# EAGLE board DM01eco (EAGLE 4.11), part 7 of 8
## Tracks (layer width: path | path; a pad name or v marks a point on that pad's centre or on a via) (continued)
GND  (via drill 0.61) (continued)
  Bottom 0.508: A09.L2 293.37,247.02 293.37,241.94 A09.N2 | v280.04,238.76 280.67,238.12 280.67,235.59 A10.R2 | 267.97,257.81 267.97,254.64 A11.J2 | 267.97,257.81 267.97,259.71 A11.F2 | 267.97,257.81 259.08,266.7 259.08,269.24 A12.C2 | 293.37,257.81 293.37,259.71 A09.F2 | 293.37,257.81 293.37,254.64 A09.J2 | 293.37,257.81 284.48,266.7 284.48,269.24 A10.C2 | v266.7,239.4 267.97,238.12 267.97,235.59 A11.R2 | 280.67,257.81 280.67,254.64 A10.J2 | 280.67,257.81 280.67,259.71 A10.F2 | 280.67,257.81 271.78,266.7 271.78,269.24 A11.C2 | 306.07,257.81 306.07,259.71 A08.F2 | 306.07,257.81 306.07,254.64 A08.J2 306.7,253.37 310.51,253.37 318.77,245.11 | 306.07,257.81 297.18,266.7 297.18,269.24 A09.C2 | 318.77,245.11 318.77,247.02 A07.L2 | 318.77,245.11 318.77,241.94 A07.N2 | 344.17,257.81 344.17,254.64 A05.J2 | 344.17,257.81 344.17,259.71 A05.F2 | 344.17,257.81 335.28,266.7 335.28,269.24 A06.C2 | B16.C2 208.28,199.39 212.09,199.39 213.36,198.12 219.07,198.12 220.34,199.39 B15.C2 220.98,199.39 222.88,199.39 223.52,198.75 225.43,198.75 226.06,198.12 v227.33,198.12 | v243.21,198.75 242.57,198.12 238.76,198.12 237.49,199.39 233.68,199.39 B14.C2 | v290.19,195.58 290.19,196.85 288.29,198.75 285.12,198.75 284.48,199.39 B10.C2 | B13.C2 246.38,199.39 250.19,199.39 251.46,198.12 257.18,198.12 258.44,199.39 B12.C2 259.08,199.39 262.89,199.39 264.16,198.12 269.88,198.12 271.14,199.39 B11.C2 271.14,200.66 271.14,203.2 266.06,208.28 260.99,208.28 248.92,220.34 248.28,220.34 244.47,224.16 244.47,229.24 241.94,231.78 241.94,232.41 237.49,236.86 234.31,236.86 233.68,237.49 A14.P2 | 140.97,236.22 140.97,240.66 A21.N2
  Bottom 0.508: 140.97,236.22 140.97,235.59 A21.R2 141.6,234.31 142.88,233.05 142.88,231.14 144.15,229.87 144.15,226.06 A21.U2 | 153.67,241.94 153.03,242.57 149.86,242.57 145.41,247.02 141.6,247.02 A21.L2 | 153.67,241.94 A20.N2 | A20.N2 153.67,240.66 153.67,235.59 A20.R2 154.31,234.31 155.57,233.05 155.57,231.14 156.84,229.87 156.84,226.06 A20.U2 | 153.67,241.94 153.67,247.02 A20.L2 153.67,248.28 153.67,250.83 151.76,252.73 149.22,252.73 147.32,250.83 140.97,257.18 | 153.67,241.94 A20.N2 | 140.97,257.18 140.97,259.71 A21.F2 140.97,260.99 140.34,261.62 137.16,261.62 132.08,266.7 132.08,269.24 A22.C2 | 140.97,257.18 140.97,254.64 A21.J2 | A21.C2 144.78,269.24 144.78,266.7 149.86,261.62 153.03,261.62 153.67,260.99 A20.F2 | 223.52,231.78 229.24,226.06 229.24,223.52 229.87,222.89 A14.V2 | 223.52,231.78 220.98,234.31 220.98,237.49 A15.P2 | v226.06,234.31 223.52,231.78 | 226.69,254.64 226.06,254.64 v223.52,257.18 214.63,266.06 | 226.69,254.64 229.87,254.64 A14.J2 | 214.63,266.06 212.09,268.6 208.91,268.6 208.28,269.24 A16.C2 207.65,269.24 206.38,267.97 200.66,267.97 199.39,269.24 195.58,269.24 A17.C2 194.94,269.24 193.68,267.97 187.96,267.97 186.69,269.24 182.88,269.24 A18.C2 | 214.63,266.06 217.81,269.24 220.34,269.24 A15.C2 | 226.69,254.64 v236.85,244.47 | 115.57,257.81 115.57,259.71 A23.F2 116.2,260.35 118.11,260.35 121.28,257.18 120.02,255.91 120.02,253.37 137.16,236.22 140.97,236.22 | 115.57,257.81 115.57,254.64 A23.J2 | 115.57,257.81 106.68,266.7 106.68,269.24 A24.C2 | A23.N2 115.57,241.94 115.57,247.02 A23.L2 115.57,248.28 111.76,248.28 102.87,257.18 | 102.87,244.47 102.87,241.94 A24.N2
  Bottom 0.508: 102.87,244.47 102.87,247.02 A24.L2 | 102.87,244.47 111.76,235.59 115.57,235.59 A23.R2 116.2,234.31 117.47,233.05 117.47,226.69 118.11,226.06 118.75,226.06 A23.U2 | 102.87,257.18 102.87,254.64 A24.J2 | 102.87,257.18 102.87,259.71 A24.F2 102.87,260.99 102.23,261.62 99.06,261.62 93.98,266.7 93.98,269.24 A25.C2 | A24.U2 106.05,226.06 102.23,226.06 100.97,227.33 99.06,227.33 97.79,226.06 97.16,226.69 95.89,226.69 92.08,230.5 92.08,233.05 90.81,234.31 A25.R2 90.17,235.59 90.17,240.66 A25.N2 90.17,241.94 89.53,242.57 86.36,242.57 81.92,247.02 78.11,247.02 A26.L2 77.47,248.28 74.3,248.28 66.67,255.91 66.67,258.44 65.41,259.71 A27.F2 65.41,260.99 65.41,263.52 | A26.J2 77.47,254.64 77.47,259.71 A26.F2 77.47,260.99 74.3,260.99 71.75,263.52 | 65.41,263.52 65.41,264.8 67.94,267.33 | 67.94,267.33 69.22,268.6 68.58,269.24 A27.C2 | 65.41,263.52 59.69,269.24 55.88,269.24 A28.C2 | 67.94,267.33 71.75,263.52 | 90.17,257.81 90.17,254.64 A25.J2 | 90.17,257.81 90.17,259.71 A25.F2 | 90.17,257.81 81.28,266.7 81.28,269.24 A26.C2 80.64,269.88 79.38,271.14 71.75,263.52 | B23.C2 119.38,199.39 123.19,199.39 124.46,198.12 130.18,198.12 131.44,199.39 B22.C2 132.08,199.39 135.89,199.39 137.16,198.12 v142.88,198.12 | v100.33,196.22 97.16,199.39 93.98,199.39 B25.C2 | B21.C2 144.78,199.39 148.59,199.39 149.86,198.12 154.94,198.12 156.84,200.03 B20.C2 157.48,199.39 161.29,199.39 168.28,192.41 170.81,192.41 172.72,194.31 170.81,196.22 170.81,198.75 170.18,199.39 B19.C2 | v191.77,198.75 189.23,196.22 186.69,198.75 183.51,198.75 182.88,199.39 B18.C2 | A32.U2 4.45,226.06 4.45,229.87 3.17,231.14 3.17,233.05 1.91,234.31 A32.R2
  Bottom 0.508: A31.U2 17.14,226.06 17.14,229.87 15.88,231.14 15.88,233.05 14.61,234.31 A31.R2 | A31.L2 13.97,247.02 13.97,241.94 A31.N2 | 13.97,257.81 13.97,254.64 A31.J2 | 13.97,257.81 13.97,259.71 A31.F2 | 8.26,263.52 13.97,257.81 | 8.26,263.52 5.08,266.7 5.08,269.24 A32.C2 | 52.07,257.81 52.07,254.64 A28.J2 52.7,253.37 56.52,253.37 64.77,245.11 | 52.07,257.81 52.07,259.71 A28.F2 | 52.07,257.81 43.18,266.7 43.18,269.24 A29.C2 | A30.L2 26.67,247.02 26.67,241.94 A30.N2 | 26.67,257.81 26.67,254.64 A30.J2 | 26.67,257.81 26.67,259.71 A30.F2 | 26.67,257.81 17.78,266.7 17.78,269.24 A31.C2 17.14,269.88 15.88,271.14 8.26,263.52 | v9.53,198.12 8.26,199.39 5.08,199.39 B32.C2 | 35.56,198.12 34.29,199.39 30.48,199.39 B30.C2 | 35.56,198.12 41.27,198.12 42.55,199.39 B29.C2 | 36.83,196.85 35.56,198.12 | 36.83,196.85 v45.72,187.96 48.9,184.78 52.07,184.78 B28.J2 | 36.83,196.85 33.66,193.68 32.38,193.68 27.94,198.12 22.86,198.12 21.59,199.39 17.78,199.39 B31.C2 | 41.27,175.9 41.27,182.25 40.01,183.52 B29.J2 | 41.27,175.9 41.27,173.99 42.55,172.72 42.55,168.91 B29.P2 | A29.U2 42.55,226.06 42.55,227.97 40.01,230.5 40.01,234.31 A29.R2 | A29.L2 39.37,247.02 39.37,241.94 A29.N2 | A26.U2 80.64,226.06 79.38,227.33 79.38,229.24 78.11,230.5 78.11,234.31 A26.R2 77.47,235.59 73.66,235.59 64.77,244.47 | 64.77,244.47 64.77,241.94 A27.N2 | 64.77,244.47 64.77,245.11 | 64.77,245.11 64.77,247.02 A27.L2 | A28.R2 52.07,235.59 52.07,240.66 A28.N2 | v76.2,197.49 73.66,197.49 72.39,198.75 69.22,198.75 68.58,199.39 B27.C2 | v87.63,196.22 85.09,198.75 81.92,198.75 81.28,199.39 B26.C2 | 358.77,198.12 353.06,198.12 351.79,199.39 347.98,199.39 B05.C2 347.35,200.03 345.44,198.12 340.36,198.12 339.09,199.39 335.28,199.39 B06.C2
  Bottom 0.508: 358.77,198.12 360.05,199.39 B04.C2 | v374.65,179.07 374.65,182.88 374.01,183.52 374.01,184.15 | 374.01,184.15 374.01,186.06 373.38,186.69 B03.H2 | v376.56,161.93 371.48,167 371.48,169.55 370.2,170.81 B03.N2 | 367.03,191.14 v368.94,193.04 | 374.01,184.15 367.03,191.14 | 358.77,198.12 359.41,198.12 366.39,191.14 367.03,191.14 | C12.C2 259.08,132.72 260.99,132.72 263.52,135.25 266.06,135.25 267.33,133.98 271.14,133.98 C11.C2 271.78,132.72 275.59,132.72 276.86,131.44 v278.13,131.44 | v379.73,129.54 376.56,132.72 373.38,132.72 C03.C2 | v391.8,128.91 391.16,128.91 389.25,127 386.71,129.54 386.71,132.08 386.08,132.72 C02.C2 | C04.C2 360.05,132.72 356.24,132.72 353.69,130.18 351.79,132.08 348.62,132.08 347.98,132.72 C05.C2 347.35,132.72 346.07,131.44 340.36,131.44 339.09,132.72 335.28,132.72 C06.C2 334.64,132.72 330.83,132.72 329.56,131.44 327.02,131.44 326.39,132.08 323.21,132.08 322.58,132.72 C07.C2 | C10.C2 284.48,132.72 288.29,132.72 289.56,131.44 295.27,131.44 296.55,132.72 C09.C2 | v377.19,140.34 373.38,144.15 373.38,154.94 B03.U2 | C17.C2 195.58,133.98 199.39,133.98 201.93,136.53 203.2,135.25 206.38,135.25 207.65,133.98 C16.C2 208.28,132.72 211.46,132.72 v214.63,129.54 | v227.33,129.54 224.16,132.72 220.98,132.72 C15.C2 | v189.23,129.54 186.69,132.08 183.51,132.08 182.88,132.72 C18.C2 | C24.C2 106.68,133.98 109.86,133.98 113.03,137.16 114.94,135.25 117.47,135.25 118.75,133.98 C23.C2 119.38,132.72 120.02,132.08 123.19,132.08 128.27,127 v130.18,127 | v99.69,131.44 99.06,131.44 97.79,132.72 93.98,132.72 C25.C2 | v11.43,129.54 8.26,132.72 5.08,132.72 C32.C2
  Bottom 0.508: C30.C2 30.48,133.98 33.66,133.98 36.83,137.16 38.73,135.25 40.64,135.25 42.55,133.35 C29.C2 | B29.V2 40.01,151.77 55.24,136.53 55.24,133.98 C28.C2 55.24,132.72 53.98,131.44 48.26,131.44 46.99,132.72 46.35,132.72 | 64.77,156.21 64.77,153.03 B27.V2 | 64.77,156.21 56.52,164.47 56.52,167 55.88,167.64 B28.P2 55.88,168.91 53.98,170.81 53.98,172.09 53.34,172.72 48.26,172.72 45.09,175.9 41.27,175.9 | v68.58,163.83 68.58,167.64 B27.P2 | 64.77,156.21 v65.41,156.84 | 46.35,132.72 43.18,132.72 | 43.18,132.72 C29.C2 | 43.18,132.72 43.81,132.08 40.64,128.91 38.1,128.91 36.83,130.18 34.92,128.27 29.84,128.27 29.21,128.91 25.4,128.91 21.59,132.72 17.78,132.72 C31.C2 | 43.18,132.72 C29.C2 | v74.93,131.44 73.03,131.44 72.39,132.08 69.22,132.08 68.58,132.72 C27.C2 | v239.4,131.44 238.12,131.44 237.49,132.08 234.31,132.08 233.68,132.72 C14.C2 | 112.39,66.67 46.35,132.72
INC_MB  (via drill 0.61)
  Top 0.152: v258.44,34.92 246.38,22.86 243.21,22.86 D13.T2 242.57,21.59 238.76,21.59 v223.52,6.35 | v66.67,12.07 96.52,12.07 101.6,17.14 107.95,17.14 111.76,20.95 114.94,20.95 115.57,21.59 D23.T2 116.2,22.86 117.47,24.13 120.65,24.13 v131.44,34.92 | 179.07,19.05 179.07,21.59 D18.T2 | 179.07,19.05 v163.19,3.18 | v193.04,33.02 179.07,19.05 | v69.85,256.54 66.04,252.73 60.96,252.73 40.01,231.78 40.01,229.24 A29.T2 | v299.72,233.05 295.27,233.05 285.12,222.89 285.12,220.98 v278.13,214 | v241.3,240.66 239.4,240.66 234.95,236.22 234.95,235.59 233.68,234.31 232.41,234.31 224.79,226.69 218.44,226.69 212.09,220.34 209.55,220.34 v207.65,218.44 | v156.84,235.59 156.84,234.95 v128.27,206.38 119.38,197.49 120.65,196.22 120.65,193.04 120.02,192.41 v120.02,191.14 | v76.83,139.06 76.83,141.61 104.78,169.55 110.49,169.55 117.47,176.53 117.47,177.8 119.38,179.71 121.28,179.71 124.46,182.88 125.73,182.88 v127,184.15
  Route2 0.152: v66.67,12.07 66.04,11.43 55.88,21.59 52.7,21.59 D28.T2 | v17.14,77.47 17.14,78.74 38.1,99.7 39.37,99.7 40.64,100.97 40.64,102.87 53.98,116.21 53.98,117.48 55.88,119.38 57.15,119.38 v76.83,139.06
  Route15 0.152: v278.13,214 274.32,214 273.69,213.36 247.01,240.03 241.94,240.03 v241.3,240.66
  Bottom 0.152: v258.44,34.92 276.86,16.51 278.13,16.51 280.04,14.61 285.12,14.61 286.38,13.34 295.91,13.34 296.55,12.7 299.72,12.7 307.34,20.32 306.07,21.59 D08.T2 | v163.19,3.18 v131.44,34.92 | v223.52,6.35 210.19,19.69 209.55,19.69 203.2,26.04 203.2,26.67 196.85,33.02 v193.04,33.02 | v69.85,256.54 72.39,256.54 76.2,252.73 81.92,252.73 102.23,232.41 | 102.23,232.41 102.23,229.87 102.87,229.24 A24.T2 | v299.72,233.05 299.72,232.41 302.89,229.24 306.07,229.24 A08.T2 | v207.65,218.44 202.56,213.36 196.85,219.08 184.78,219.08 180.34,223.52 174.62,223.52 173.99,224.16 168.28,224.16 v156.84,235.59 | v128.27,206.38 102.23,232.41 | v17.14,77.47 15.88,76.2 15.88,68.58 28.57,55.88 28.57,43.18 48.9,22.86 52.07,22.86 D28.T2 | v127,184.15 125.73,184.15 120.02,189.87 v120.02,191.14
IOP1  (via drill 0.61)
  Top 0.152: v403.86,85.09 402.59,83.82 402.59,79.38 403.23,78.74 403.23,73.03 400.69,70.48 400.69,68.58 398.78,66.67 403.86,61.59 403.86,59.69 389.25,45.09 386.08,45.09 D02.K2 | v389.25,169.55 389.89,169.55 400.05,179.71 400.05,183.52 399.42,184.15 400.05,184.78 400.05,185.42 v405.13,190.5 | v368.3,234.95 368.3,236.22 381,248.92 384.18,248.92 385.44,250.19 A02.K2
  Route2 0.152: v403.86,85.09 403.86,86.36 398.14,92.08 403.86,97.79 v403.86,98.43 | v386.08,116.21 386.08,117.48 v402.59,133.98
  Route15 0.152: v403.86,98.43 403.86,99.06 386.71,116.21 v386.08,116.21
  Bottom 0.152: v402.59,133.98 405.13,136.53 402.59,139.06 402.59,148.59 405.13,151.13 405.13,152.4 389.89,167.64 389.89,168.91 v389.25,169.55 | v405.13,190.5 399.42,196.22 399.42,198.12 401.32,200.03 374.65,226.69 374.65,227.97 368.3,234.31 v368.3,234.95
IOP2  (via drill 0.61)
  Top 0.152: v371.48,20.95 385.44,34.92 385.44,37.47 D02.M2 | v203.84,194.94 205.74,194.94 254,243.21 255.27,243.21 v258.44,246.38
  Route2 0.152: v219.07,162.56 219.07,166.37 217.17,168.28 222.25,173.36 222.25,174.62 v223.52,175.9 | v258.44,246.38 258.44,247.02 276.86,265.43 283.21,265.43 289.56,271.78 295.91,271.78 v311.15,287.02
  Route15 0.152: v269.88,98.43 269.88,99.7 259.71,109.86 259.08,109.86 257.81,111.12 257.81,112.4 244.47,125.73 244.47,137.8 231.78,150.5 229.24,150.5 219.07,160.66 v219.07,162.56
  Bottom 0.152: v371.48,20.95 356.87,6.35 311.15,52.07 311.15,53.34 310.51,53.98 310.51,55.88 311.79,57.15 310.51,58.42 305.44,58.42 269.88,93.98 v269.88,98.43 | v223.52,175.9 222.88,175.9 v203.84,194.94 | v311.15,287.02 340.36,287.02 381,246.38 384.18,246.38 385.44,245.11 A02.M2
IOP4  (via drill 0.61)
  Top 0.152: v269.24,214.63 269.88,214.63 282.57,227.33 282.57,233.05 320.68,271.14 327.02,271.14 327.66,271.78 334.01,271.78 340.36,278.13 v356.87,278.13 | v388.62,245.75 388.62,243.84 386.71,241.94 386.71,239.4 386.08,238.76 A02.P2
  Route2 0.152: v232.41,177.16 238.76,183.52 238.76,184.15 240.03,185.42 240.66,185.42 245.75,190.5 245.75,191.14 247.01,192.41 248.28,192.41 254,198.12 259.71,198.12 267.33,205.74 267.33,210.82 267.97,211.46 267.97,213.36 v269.24,214.63
  Route15 0.152: v232.41,177.16 231.78,176.53 231.78,173.36 242.57,162.56 241.3,161.29 241.3,157.48 248.28,150.5 248.92,150.5 258.44,140.97 259.71,140.97 261.62,139.06 262.25,139.06 269.88,131.44 269.88,126.37 273.05,123.19 273.05,121.92 292.1,102.87 292.1,102.23 298.45,95.89 299.08,95.89 312.42,82.55 314.32,82.55 320.04,76.84 320.04,69.22 320.68,68.58 320.68,62.23 346.07,36.83 351.79,36.83 358.14,30.48 364.49,30.48 372.75,22.23 381.63,31.12 385.44,31.12 D02.P2
  Bottom 0.152: v356.87,278.13 356.87,276.86 387.99,245.75 v388.62,245.75
MPX0  (via drill 0.61)
  Top 0.152: v29.84,210.82 29.84,215.27 50.8,236.22 56.52,236.22 v99.69,279.4 | v244.47,190.5 244.47,189.87 243.84,189.23 238.76,189.23 237.49,187.96 237.49,187.33 236.22,186.06 231.78,186.06 230.5,184.78 B14.J2 | v318.77,155.58 350.52,187.33 347.35,190.5 347.35,193.04 B05.E2 | v295.27,177.16 297.81,179.71 v299.08,179.71
  Route2 0.152: v29.84,210.82 28.57,209.55 28.57,202.56 27.3,201.3 27.3,197.49 B30.D2 | v228.6,178.44 228.6,180.34 229.24,180.97 229.24,182.88 229.87,183.52 B14.J2 | v273.69,200.03 269.88,196.22 269.88,189.23 259.08,178.44 259.08,175.26 B12.M2 | v217.81,281.3 217.17,280.67 212.09,280.67 209.55,278.13 206.38,278.13 188.59,260.35 186.69,262.25 184.78,262.25 156.21,233.68 149.86,233.68 148.59,232.41 144.78,232.41 A21.S2
  Route15 0.152: v228.6,178.44 228.6,177.16 231.14,174.62 231.14,173.36 233.04,171.45 233.04,168.91 B14.P2 | v244.47,190.5 246.38,188.59 247.65,188.59 255.27,180.97 254,179.71 254,177.16 255.91,175.26 258.44,175.26 B12.M2 | v299.08,179.71 295.91,179.71 295.27,180.34 295.27,181.61 297.18,183.52 282.57,198.12 | 282.57,198.12 282.57,211.46 257.18,236.86 257.18,243.21 244.47,255.91 244.47,261.62 245.75,262.89 A13.E2 | v273.69,200.03 274.95,200.03 276.86,198.12 282.57,198.12
  Bottom 0.152: v99.69,279.4 106.05,279.4 142.88,242.57 142.88,234.31 144.78,232.41 A21.S2 | v318.77,155.58 298.45,175.9 296.55,175.9 v295.27,177.16 | v217.81,281.3 225.43,281.3 241.3,265.43 243.84,265.43 245.75,263.52 A13.E2
MPX1  (via drill 0.61)
  Top 0.152: v66.67,168.91 67.31,169.55 72.39,169.55 116.2,213.36 116.84,213.36 139.7,236.22 142.88,236.22 144.15,237.49 A21.P2 | v203.2,182.25 204.47,183.52 B16.J2 | B13.D2 243.21,197.49 243.84,197.49 244.47,198.12 v245.75,198.12 246.38,198.75 247.65,198.75 | v233.68,235.59 242.57,244.47 241.3,245.75 241.3,248.92 242.57,250.19 241.3,251.46 241.3,254.64 243.21,256.54 245.75,256.54 A13.H2 | v255.27,212.09 255.27,206.38 247.65,198.75 | v328.3,170.18 332.74,174.62 332.74,175.26 344.17,186.69 347.35,186.69 B05.H2 | v306.7,192.41 305.44,192.41 295.27,182.25 295.27,181.61 v290.19,176.53 | v261.62,194.94 261.62,194.31 259.71,192.41 258.44,192.41 255.91,189.87 B12.F2 | v204.47,173.36 209.55,173.36 228.6,192.41 237.49,192.41 239.4,190.5 247.65,198.75 | v158.75,219.71 159.38,219.71 160.02,219.08 v172.09,219.08
  Route15 0.152: v290.19,176.53 289.56,176.53 287.65,174.62 275.59,186.69 275.59,187.33 274.32,188.59 267.33,188.59 261.62,194.31 v261.62,194.94 | v172.09,219.08 175.9,215.27 175.9,214.63 182.88,207.65 183.51,207.65 186.06,205.11 186.69,205.11 193.68,198.12 193.68,191.77 v203.2,182.25
  Bottom 0.152: v66.67,168.91 66.67,172.72 55.88,183.52 51.44,179.07 48.26,179.07 40.01,187.33 34.29,181.61 30.48,181.61 B30.K2 | 205.1,173.36 207.65,170.81 207.65,168.91 B16.P2 | 205.1,173.36 205.1,174.62 202.56,177.16 202.56,177.8 201.29,179.07 200.66,179.07 199.39,180.34 199.39,181.61 201.29,183.52 201.93,182.88 202.56,182.88 v203.2,182.25 | v245.75,198.12 245.75,197.49 251.46,191.77 254.63,191.77 255.27,191.14 B12.F2 | v233.68,235.59 233.68,234.95 241.3,227.33 241.3,226.06 v255.27,212.09 | v328.3,170.18 328.3,171.45 307.34,192.41 v306.7,192.41 | v204.47,173.36 205.1,173.36 | v158.75,219.71 158.75,220.34 144.78,234.31 144.78,237.49 A21.P2
MPX2  (via drill 0.61)
  Top 0.152: v69.22,185.42 69.85,185.42 92.08,207.65 93.98,207.65 100.97,214.63 103.5,214.63 107.95,219.08 111.76,219.08 116.84,214 142.88,240.03 142.88,242.57 144.15,243.84 A21.M2 | 239.4,189.87 242.57,189.87 B13.F2 | 239.4,189.87 238.76,189.87 237.49,188.59 236.22,188.59 235.59,187.96 231.78,191.77 228.6,191.77 212.72,175.9 212.72,175.26 210.82,173.36 210.19,173.36 205.74,168.91 205.1,168.91 201.29,165.1 198.75,167.64 195.58,167.64 B17.P2 195.58,168.91 196.22,169.55 v196.22,170.81 | v261.62,182.25 259.71,182.25 259.08,181.61 B12.K2 | v244.47,241.3 244.47,245.11 245.75,246.38 245.75,250.19 A13.K2 | v256.54,216.53 256.54,207.01 239.4,189.87
  Route2 0.152: v36.83,158.12 39.37,155.58 v69.22,185.42 | v256.54,179.71 257.18,180.34 258.44,180.34 B12.K2 | v305.44,139.06 317.5,151.13 320.04,151.13 325.75,156.84 327.02,156.84 343.54,173.36 348.62,173.36 349.88,174.62 347.98,176.53 347.98,180.34 B05.K2
  Bottom 0.152: v36.83,158.12 30.48,164.47 27.3,164.47 B30.R2 | v256.54,179.71 247.65,188.59 245.11,188.59 243.21,190.5 B13.F2 | v305.44,139.06 303.53,137.16 302.89,137.8 302.26,137.8 292.74,147.32 292.74,147.96 290.83,149.86 290.19,149.86 288.93,151.13 290.19,152.4 291.46,152.4 292.74,151.13 294.64,151.13 295.91,152.4 294.64,153.67 289.56,153.67 261.62,181.61 v261.62,182.25 | v196.22,170.81 195.58,171.45 196.85,172.72 196.85,175.26 192.41,179.71 192.41,183.52 B17.J2 191.77,184.78 191.13,185.42 191.13,187.96 186.69,192.41 186.69,193.68 185.42,194.94 184.78,194.94 176.53,203.2 174.62,201.3 172.09,201.3 170.18,203.2 171.45,204.47 171.45,207.01 165.1,213.36 165.1,215.9 160.66,220.34 159.38,220.34 155.57,224.16 155.57,229.87 144.78,240.66 144.78,243.84 A21.M2 | v244.47,241.3 244.47,230.5 252.09,222.89 252.09,220.98 v256.54,216.53
MPX3  (via drill 0.61)
  Top 0.152: v12.06,208.28 7.62,208.28 1.91,214 3.81,215.9 3.81,216.53 6.35,219.08 7.62,219.08 53.98,265.43 53.98,270.51 54.61,271.14 59.69,271.14 60.96,272.41 62.23,272.41 64.14,274.32 69.22,274.32 73.66,278.76 83.82,278.76 85.09,280.03 88.9,280.03 v89.53,280.67 | B13.J2 243.21,184.78 247.01,184.78 254,191.77 257.18,191.77 258.44,193.04 B12.E2 258.44,194.31 258.44,196.85 264.8,203.2 | v273.05,215.27 273.05,211.46 264.8,203.2 | v264.16,203.84 264.8,203.2 | 189.23,214.63 191.13,212.72 191.13,205.74 182.88,197.49 184.15,196.22 184.15,193.04 182.25,191.14 184.15,189.23 184.15,186.69 182.25,184.78 179.71,184.78 B18.J2 | 189.23,214.63 193.68,219.08 198.12,219.08 199.39,220.34 205.1,220.34 211.46,226.69 212.09,226.69 230.5,245.11 v230.5,245.75 | v148.59,250.19 151.13,247.65 v156.84,253.37 | v190.5,221.62 190.5,220.98 181.61,212.09 184.15,209.55 189.23,214.63
  Route2 0.152: v317.5,158.75 316.87,158.12 317.5,157.48 320.04,157.48 321.31,158.75 322.58,158.75 333.38,169.55 339.09,169.55 343.54,173.99 347.35,173.99 B05.M2
  Route15 0.152: 246.38,241.3 246.38,243.84 A13.M2 | 246.38,241.3 272.42,215.27 v273.05,215.27 | v317.5,158.75 315.6,158.75 282.57,191.77 276.23,191.77 273.69,194.31 273.05,194.31 266.7,200.66 266.7,201.3 v264.16,203.84 | v230.5,245.75 238.12,245.75 240.03,247.65 246.38,241.3
  Bottom 0.152: v12.06,208.28 17.14,203.2 14.61,200.66 14.61,197.49 B31.D2 | v89.53,280.67 111.76,280.67 139.7,252.73 142.88,252.73 144.15,251.46 A21.K2 144.78,250.19 v148.59,250.19 | B18.P2 182.25,168.91 182.25,172.72 180.97,173.99 180.97,179.71 179.71,180.97 179.71,183.52 B18.J2 | v156.84,253.37 157.48,253.37 165.1,245.75 165.1,245.11 173.35,236.86 173.99,236.86 187.96,222.89 189.23,222.89 v190.5,221.62
MPX4  (via drill 0.61)
  Top 0.152: v252.73,185.42 252.73,184.78 246.38,178.44 243.21,178.44 B13.L2 | v257.81,218.44 257.18,218.44 255.27,216.53 255.27,213.36 v248.92,207.01 | v29.84,176.53 29.84,177.16 71.75,219.08 71.75,219.71 88.9,236.86 90.17,236.86 92.71,239.4 97.79,239.4 109.86,251.46 110.49,251.46 116.84,257.81 117.47,257.81 120.65,260.99 120.65,261.62 130.18,271.14 v134.62,271.14 | v156.21,191.77 154.31,193.68 158.12,197.49 158.12,198.75 158.75,199.39 158.75,202.56 157.48,203.84 158.75,205.11 158.75,208.28 160.02,209.55 167.64,209.55 174.62,216.53 174.62,218.44 v177.8,221.62
  Route2 0.152: v372.11,220.34 370.84,219.08 370.84,212.72 368.94,210.82 368.94,205.74 364.49,201.3 363.22,201.3 361.95,200.03 361.95,199.39 360.05,197.49 361.95,195.58 361.95,193.04 360.68,191.77 360.68,191.14 353.69,184.15 356.24,181.61 356.24,180.34 347.98,172.09 347.98,168.91 B05.P2 | v311.15,275.59 311.15,274.32 288.93,252.09 287.65,252.09 285.12,249.56 281.94,249.56 277.5,254 265.43,241.94 264.8,241.94 263.52,240.66 263.52,240.03 260.35,236.86 254.63,236.86 250.19,232.41 250.19,231.14 v249.56,230.5 | B19.P2 169.54,168.91 169.54,172.72 163.83,178.44 165.74,180.34 165.74,182.88 166.37,183.52 B19.J2 | v192.41,243.21 190.5,243.21 169.54,222.25 168.91,222.25 167.64,220.98 172.09,216.53 177.16,221.62 v177.8,221.62
  Route15 0.152: 245.11,203.2 242.57,200.66 244.47,198.75 244.47,198.12 254.63,187.96 254.63,185.42 255.27,184.78 B12.J2 | v248.92,207.01 245.11,203.2 | v372.11,220.34 372.11,222.89 351.79,243.21 346.07,243.21 314.32,274.95 311.79,274.95 v311.15,275.59 | v177.8,221.62 177.16,221.62 152.4,246.38 149.86,246.38 147.96,244.47 145.41,247.02 145.41,247.65 142.88,250.19 142.88,255.27 138.43,259.71 138.43,260.35 140.97,262.89 142.88,260.99 142.88,259.08 144.15,257.81 A21.H2 | 245.11,203.2 245.11,203.84 240.66,208.28 234.95,208.28 223.52,219.71 222.88,219.71 199.39,243.21 v192.41,243.21
  Bottom 0.152: v252.73,185.42 254.63,185.42 255.27,184.78 B12.J2 | 249.56,231.14 257.18,223.52 257.18,219.08 v257.81,218.44 | 249.56,231.14 246.38,234.31 246.38,237.49 A13.P2 | v249.56,230.5 249.56,231.14 | v29.84,176.53 25.4,176.53 21.59,180.34 17.78,180.34 B31.K2 | v134.62,271.14 134.62,269.88 142.88,261.62 142.88,259.08 144.15,257.81 A21.H2 | v156.21,191.77 163.19,184.78 166.37,184.78 B19.J2
MPX5  (via drill 0.61)
  Top 0.152: v257.81,217.17 257.81,215.9 257.18,215.27 257.18,198.75 255.91,197.49 B12.D2 | v296.55,150.5 288.29,142.24 288.29,140.34 v283.85,135.89 | v153.03,180.97 153.03,182.88 153.67,183.52 B20.J2 154.31,184.78 156.84,184.78 158.75,186.69 159.38,186.69 | v29.21,153.03 30.48,153.03 62.87,185.42 64.14,185.42 67.31,188.59 72.39,188.59 92.08,208.28 93.98,208.28 100.97,215.27 103.5,215.27 107.95,219.71 110.49,219.71 118.11,227.33 | 118.11,227.33 146.69,255.91 v147.32,255.91 | v160.02,186.06 159.38,186.69 | 118.11,227.33 v118.75,227.33 | v169.54,189.87 166.37,193.04 160.02,186.69 159.38,186.69
  Route2 0.152: v244.47,174.62 243.21,173.36 243.21,172.09 B13.N2 | v245.11,183.52 254.63,193.04 254.63,195.58 255.27,196.22 B12.D2 | v318.13,139.06 321.94,142.88 321.94,144.78 334.01,156.84 339.73,156.84 344.17,161.29 347.35,161.29 B05.S2 | v197.49,220.34 194.31,220.34 177.8,203.84 177.8,201.93 179.71,200.03 v169.54,189.87
  Route15 0.152: v257.81,217.17 246.38,228.6 246.38,231.14 A13.S2 | v283.85,135.89 283.85,136.53 278.76,141.61 276.23,141.61 262.89,154.94 262.89,156.84 264.8,158.75 262.89,160.66 257.81,160.66 254,164.47 254,167 255.27,168.28 250.19,173.36 245.11,173.36 244.47,173.99 v244.47,174.62 | v245.11,183.52 245.11,184.15 243.84,185.42 238.76,185.42 237.49,186.69 237.49,187.33 236.22,188.59 235.59,188.59 215.9,208.28 210.82,208.28 200.66,218.44 200.66,219.08 199.39,220.34 v197.49,220.34
  Bottom 0.152: v244.47,174.62 244.47,182.88 v245.11,183.52 | v318.13,139.06 315.6,136.53 313.69,138.43 307.98,138.43 299.72,146.69 299.72,147.32 v296.55,150.5 | v153.03,180.97 155.57,178.44 155.57,173.99 156.84,172.72 156.84,168.91 B20.P2 | v29.21,153.03 17.78,164.47 14.61,164.47 B31.R2 | v147.32,255.91 146.05,257.18 146.05,259.71 145.41,260.35 145.41,262.25 144.78,262.89 A21.E2 | v160.02,186.06 160.02,186.69 158.12,188.59 153.03,188.59 144.15,197.49 144.15,198.12 139.7,202.56 139.7,205.11 140.97,206.38 120.65,226.69 119.38,226.69 v118.75,227.33
MPX6  (via drill 0.61)
  Top 0.152: v102.87,220.34 103.5,220.98 104.78,220.98 112.39,228.6 110.49,230.5 110.49,232.41 117.47,239.4 117.47,245.11 118.11,245.75 123.19,245.75 140.97,263.52 140.97,266.06 A21.D2 141.6,267.33 141.6,269.24 143.51,271.14 149.22,271.14 149.86,271.78 154.94,271.78 155.57,272.41 v155.57,276.86 | v246.38,160.02 249.56,163.19 250.19,163.19 260.99,173.99 260.99,174.62 262.25,175.9 262.89,175.9 v268.61,181.61 | v335.92,137.16 345.44,146.69 345.44,149.22 346.71,150.5 346.71,152.4 347.35,153.03 347.35,154.94 B05.U2
  Route2 0.152: v292.74,161.93 292.74,163.19 281.94,173.99 v282.57,174.62
  Route15 0.152: 141.6,180.34 141.6,179.71 142.88,178.44 142.88,173.36 143.51,172.72 143.51,169.55 144.15,168.91 B21.P2 | 141.6,180.34 141.6,183.52 B21.J2 | v128.27,188.59 133.35,188.59 141.6,180.34 | v102.87,220.34 102.87,212.72 114.94,200.66 114.94,198.12 115.57,197.49 B23.D2 | 271.14,184.15 v268.61,181.61 | 271.14,184.15 260.35,194.94 259.71,194.94 258.44,196.22 258.44,198.12 257.18,199.39 257.18,211.46 247.01,221.62 247.01,222.25 | 247.01,222.25 247.01,224.16 246.38,224.79 A13.U2 | v282.57,174.62 282.57,178.44 281.94,179.07 276.86,179.07 275.59,180.34 275.59,180.97 274.32,182.25 273.05,182.25 271.14,184.15 | v155.57,276.86 160.02,281.3 161.93,281.3 177.8,265.43 183.51,265.43 203.2,245.75 210.19,245.75 215.9,240.03 222.25,240.03 226.06,236.22 231.78,236.22 238.12,229.87 239.4,229.87 247.01,222.25
  Bottom 0.152: v128.27,188.59 125.73,191.14 124.46,191.14 119.38,196.22 116.2,196.22 B23.D2 | v246.38,160.02 245.75,160.02 243.21,162.56 243.21,164.47 B13.R2 | v335.92,137.16 332.11,133.35 329.56,135.89 328.93,135.89 323.85,140.97 321.94,140.97 316.87,146.05 314.96,146.05 307.34,153.67 302.26,153.67 298.45,157.48 297.18,157.48 v292.74,161.93
N$1  (via drill 0.61)
  Top 0.152: B21.U2 144.15,154.94 144.15,153.67 142.88,152.4 142.88,147.32 141.6,146.05 143.51,144.15 153.03,153.67 155.57,153.67 156.84,154.94 B20.U2 157.48,156.21 157.48,159.39 165.74,167.64 165.74,170.18 166.37,170.81 B19.N2 | 175.26,157.48 173.99,156.21 170.18,156.21 B19.U2 | 181.61,157.48 175.26,157.48 | 181.61,157.48 182.88,156.21 B18.U2 | 175.26,157.48 179.07,161.29 177.8,162.56 177.8,165.74 179.71,167.64 179.71,170.81 B18.N2 | 191.77,168.28 191.77,167.64 181.61,157.48 | 191.77,168.28 191.77,170.81 B17.N2 | 191.77,168.28 198.12,174.62 200.66,172.09 204.47,172.09 B16.N2 | v147.32,175.26 144.15,172.09 141.6,172.09 B21.N2 | v192.41,225.43 163.19,196.22 162.56,196.22 v144.78,178.44 | B16.U2 208.28,156.21 211.46,156.21 225.43,170.18 229.24,170.18 229.87,170.81 B14.N2 | v309.25,141.61 315.6,147.96 318.13,145.41 322.58,145.41 323.85,146.69 323.85,147.32 353.06,176.53 353.69,176.53 361.31,184.15 361.31,184.78 366.39,189.87 369.57,189.87 B03.F2 | v262.25,186.69 260.99,186.69 234.95,160.66 234.95,159.39 234.31,158.75 234.31,156.84 233.68,156.21 B14.U2
  Bottom 0.152: 185.42,161.93 184.15,163.19 180.97,163.19 179.71,161.93 | 185.42,161.93 191.13,156.21 194.94,156.21 B17.U2 | 179.71,161.93 179.07,161.29 180.97,159.39 180.97,157.48 182.25,156.21 B18.U2 | 179.71,161.93 170.81,170.81 167,170.81 B19.N2 | v192.41,225.43 170.18,247.65 170.18,250.19 A19.K2 | v144.78,178.44 144.78,177.8 v147.32,175.26 149.86,172.72 153.03,172.72 153.67,172.09 B20.N2 154.31,170.81 155.57,169.55 155.57,167 166.37,156.21 169.54,156.21 B19.U2 | B14.U2 233.04,156.21 233.04,160.02 231.78,161.29 231.78,166.37 226.69,171.45 228.6,173.36 229.87,172.09 B14.N2 | v309.25,141.61 308.61,141.61 300.99,149.22 300.36,149.22 271.78,177.8 271.14,177.8 v262.25,186.69 | 185.42,161.93 188.59,165.1 189.23,165.1 200.66,153.67 206.38,153.67 207.65,154.94 B16.U2
N$2  (via drill 0.61)
  Top 0.152: B14.F2 229.87,189.87 229.24,189.23 229.24,186.69 v217.17,174.62 208.28,165.74 205.1,165.74 B16.R2 204.47,164.47 202.56,164.47 201.93,163.83 200.66,163.83 198.12,161.29 v198.12,160.66 | B18.F2 179.07,189.87 175.26,189.87 173.99,188.59 168.28,188.59 167,189.87 B19.F2 | B19.R2 167,165.74 167,167.64 168.91,169.55 173.99,169.55 v176.53,172.09 191.13,186.69 191.13,189.23 191.77,189.87 B17.F2 | v198.12,186.06 198.12,186.69 201.29,189.87 204.47,189.87 B16.F2 | v147.32,168.91 144.15,165.74 141.6,165.74 B21.R2 | v41.91,219.71 40.01,219.71 5.08,184.78 1.91,184.78 B32.J2 | v106.05,158.75 136.53,189.23 137.16,189.23 | 137.16,189.23 140.34,189.23 140.97,189.87 B21.F2 141.6,191.14 142.88,192.41 142.88,194.94 156.84,208.91 v156.84,209.55 | v137.79,228.6 166.37,257.18 166.37,259.71 A19.F2 | v135.25,180.97 132.08,184.15 137.16,189.23 | v147.32,186.69 150.5,189.87 153.67,189.87 B20.F2
  Bottom 0.152: v217.17,174.62 228.6,163.19 228.6,162.56 229.24,161.93 228.6,161.29 228.6,158.12 230.5,156.21 231.78,157.48 231.78,159.39 230.5,160.66 230.5,164.47 B14.R2 | 170.18,184.78 168.28,182.88 165.74,182.88 164.47,184.15 163.19,184.15 157.48,189.87 154.31,189.87 B20.F2 | 170.18,184.78 168.28,186.69 168.28,188.59 167,189.87 B19.F2 | 179.71,165.74 183.51,165.74 186.06,168.28 187.96,166.37 188.59,166.37 | 188.59,166.37 191.13,166.37 191.77,165.74 B17.R2 | 179.71,165.74 B18.R2 179.71,165.74 | v198.12,186.06 198.12,186.69 196.22,188.59 193.68,188.59 192.41,189.87 B17.F2 | 179.71,165.74 179.71,168.91 v176.53,172.09 178.44,173.99 178.44,175.26 176.53,177.16 179.07,179.71 178.44,180.34 178.44,181.61 172.72,187.33 170.18,184.78 | v198.12,160.66 194.31,160.66 188.59,166.37 | B20.R2 153.67,165.74 153.03,166.37 149.86,166.37 v147.32,168.91 v135.25,180.97 | v41.91,219.71 45.09,219.71 v106.05,158.75 | v156.84,209.55 v137.79,228.6 | v147.32,186.69 145.41,188.59 142.88,188.59 141.6,189.87 B21.F2
N$3  (via drill 0.61)
  Top 0.152: v113.67,280.03 113.03,280.67 99.69,280.67 97.16,278.13 86.36,278.13 85.72,277.5 79.38,277.5 67.31,265.43 60.33,265.43 13.34,218.44 13.34,205.74 1.91,194.31 1.91,191.14 B32.F2 | v156.21,260.35 157.48,260.35 162.56,265.43 168.28,265.43 177.8,274.95 184.15,274.95 187.96,278.76 196.85,278.76 v203.84,285.75
  Route2 0.152: v236.85,262.25 236.85,263.52 251.46,278.13 263.52,278.13 264.16,278.76 268.61,278.76 270.51,280.67 274.95,280.67 v282.57,288.29 | v393.06,240.03 391.16,240.03 374.01,222.89 374.01,211.46 372.75,210.19 372.75,208.91 364.49,200.66 364.49,198.75 366.39,196.85 361.31,191.77 361.31,191.14 355.6,185.42 355.6,183.52 358.14,180.97 359.41,182.25 365.12,182.25 365.76,182.88 368.94,182.88 369.57,183.52 B03.J2
  Bottom 0.152: v113.67,280.03 137.16,280.03 156.21,260.99 v156.21,260.35 | v203.84,285.75 207.65,285.75 225.43,267.97 231.14,267.97 v236.85,262.25 | v282.57,288.29 344.81,288.29 v393.06,240.03
N$4  (via drill 0.61)
  Top 0.152: v41.27,244.47 41.27,233.68 13.97,206.38 13.97,205.74 3.17,194.94 3.17,189.87 v1.91,188.59 | v8.89,173.99 11.43,171.45 3.17,163.19 3.17,160.66 1.91,159.39 B32.T2
  Bottom 0.152: v41.27,244.47 41.27,248.92 11.43,278.76 11.43,287.02 10.16,288.29 PDP-12/8I/8.3 | v1.91,188.59 1.91,186.06 3.17,184.78 3.17,179.71 v8.89,173.99
N$5  (via drill 0.61)
  Top 0.152: 1.91,178.44 5.71,178.44 10.16,182.88 16.51,182.88 20.95,187.33 | 20.95,187.33 38.1,204.47 39.37,204.47 41.27,206.38 41.27,207.01 44.45,210.19 45.09,210.19 47.62,212.72 47.62,214 75.56,241.94 v76.2,241.94 | v120.02,213.36 128.91,213.36 172.09,256.54 172.72,256.54 187.96,271.78 194.31,271.78 200.66,278.13 202.56,278.13 v210.82,286.38 | 20.95,187.33 v19.05,187.33
  Route2 0.152: v233.04,272.41 236.22,269.24 238.76,271.78 243.84,271.78 251.46,279.4 255.27,279.4 257.18,281.3 265.43,281.3 v271.14,287.02 | v380.37,191.14 374.01,184.78 374.01,182.25 373.38,181.61 B03.K2 | v357.5,186.06 357.5,186.69 361.95,191.14 361.95,191.77 v370.84,200.66 | v38.1,152.4 31.11,145.41 31.11,143.51 28.57,140.97 28.57,135.25 5.08,111.76 5.08,108.59 C32.M2
  Route15 0.152: v357.5,186.06 358.77,184.78 358.77,180.34 361.95,177.16 361.95,176.53 369.57,168.91 369.57,165.74 B03.R2 | v38.1,152.4 38.1,154.31 45.72,161.93 21.59,186.06 20.32,186.06 v19.05,187.33
  Bottom 0.152: v76.2,241.94 78.11,243.84 91.44,230.5 91.44,229.87 95.25,226.06 96.52,226.06 99.06,223.52 105.41,223.52 108.58,220.34 113.03,220.34 v120.02,213.36 | v210.82,286.38 211.46,286.38 217.81,280.03 226.06,280.03 233.04,273.05 v233.04,272.41 | v271.14,287.02 281.31,287.02 282.57,285.75 289.56,285.75 290.19,285.11 293.37,285.11 295.27,283.21 299.08,283.21 320.68,261.62 320.68,255.27 333.38,242.57 333.38,236.86 368.3,201.93 370.84,201.93 | 370.84,201.93 374.01,201.93 381.63,194.31 381.63,192.41 v380.37,191.14 | 370.84,201.93 v370.84,200.66
N$6  (via drill 0.61)
  Top 0.152: v151.13,177.8 151.76,177.8 153.03,179.07 155.57,179.07 156.84,180.34 B20.K2 | v177.8,179.71 178.44,180.34 182.25,180.34 B18.K2 182.25,181.61 182.25,184.15 191.13,193.04 191.13,194.31 v191.77,194.94 | v201.29,177.8 202.56,177.8 203.84,179.07 206.38,179.07 207.65,180.34 B16.K2 208.28,181.61 208.91,182.25 212.09,182.25 v215.9,186.06 | v360.05,184.15 v322.58,146.69 | v284.48,184.15 v259.71,159.39 | v235.59,182.25 234.31,182.25 233.68,181.61 B14.K2
  Route2 0.152: v151.13,177.8 148.59,180.34 144.78,180.34 B21.K2
  Route15 0.152: v215.9,186.06 224.79,186.06 229.24,181.61 233.04,181.61 B14.K2
  Bottom 0.152: B20.K2 157.48,181.61 159.38,179.71 161.29,179.71 163.19,177.8 165.74,180.34 169.54,180.34 B19.K2 170.18,180.34 170.81,179.71 173.99,179.71 175.9,177.8 v177.8,179.71 | v201.29,177.8 198.75,180.34 195.58,180.34 B17.K2 | v360.05,184.15 368.94,175.26 372.75,175.26 B03.M2 | v322.58,146.69 321.94,146.69 v284.48,184.15 | v259.71,159.39 258.44,159.39 v235.59,182.25 | v191.77,194.94 196.85,194.94 206.38,185.42 206.38,182.88 207.65,181.61 B16.K2
N$7  (via drill 0.61)
  Top 0.152: v215.9,169.55 215.9,172.09 222.25,178.44 222.25,179.07 228.6,185.42 230.5,185.42 233.04,187.96 B14.H2
  Bottom 0.152: v215.9,169.55 229.87,155.58 229.87,153.03 B14.V2
N$8
  Top 0.152: C32.J2 1.91,116.84 4.45,114.3 C32.K2
N$9  (via drill 0.61)
  Top 0.152: v223.52,173.36 222.88,173.36 220.98,171.45 222.25,170.18 222.25,167.64 218.44,163.83 213.36,163.83 205.1,155.58 205.1,153.03 B16.V2
  Bottom 0.152: v223.52,173.36 223.52,174.62 212.09,186.06 208.91,186.06 208.28,186.69 B16.H2
N$10  (via drill 0.61)
  Top 0.152: v1.27,160.66 1.27,162.56 6.35,167.64 6.35,170.18 1.91,174.62 3.17,175.9 1.91,177.16 B32.L2
  Bottom 0.152: v1.27,160.66 1.91,160.66 3.17,159.39 3.17,154.94 4.45,153.67 4.45,152.4 6.35,150.5 6.35,147.96 6.99,147.32 6.99,139.7 7.62,139.06 3.17,134.62 3.17,132.08 6.35,128.91 5.08,127.64 C32.E2
N$11  (via drill 0.61)
  Top 0.152: v206.38,162.56 204.47,160.66 203.2,160.66 199.39,156.84 194.31,156.84 192.41,154.94 192.41,153.03 B17.V2
  Bottom 0.152: v206.38,162.56 205.1,163.83 203.84,163.83 201.93,165.74 204.47,168.28 196.85,175.9 196.85,177.16 193.68,180.34 193.68,185.42 194.94,186.69 B17.H2
N$13  (via drill 0.61)
  Top 0.152: v163.83,171.45 177.8,185.42 180.97,185.42 182.25,186.69 B18.H2
  Bottom 0.152: v163.83,171.45 179.07,156.21 179.07,153.03 B18.V2
N$15  (via drill 0.61)
  Top 0.152: v153.03,168.91 154.31,168.91 168.28,182.88 168.28,185.42 169.54,186.69 B19.H2
  Bottom 0.152: v153.03,168.91 166.37,155.58 166.37,153.03 B19.V2
N$17  (via drill 0.61)
  Top 0.152: v139.06,170.18 139.06,171.45 146.05,178.44 146.05,179.07 152.4,185.42 155.57,185.42 156.84,186.69 B20.H2
  Bottom 0.152: v139.06,170.18 153.67,155.58 153.67,153.03 B20.V2
N$19
  Route2 0.152: B21.V2 140.97,153.03 140.97,155.58 134.62,161.93 140.34,167.64 140.34,170.18 138.43,172.09 140.34,173.99 140.34,176.53 139.06,177.8 143.51,182.25 143.51,186.06 144.15,186.69 B21.H2
N$21  (via drill 0.61)
  Top 0.152: v79.38,123.83 80.01,123.83 82.55,126.37 82.55,128.91 81.28,130.18 92.08,140.97 93.34,140.97 96.52,144.15 97.79,144.15 117.47,163.83 117.47,166.37 118.75,167.64 B23.P2
  Bottom 0.152: B23.P2 118.75,168.91 118.11,168.91 116.2,170.81 B23.N2 | v79.38,123.83 79.38,124.46 78.74,125.09 73.66,125.09 48.26,150.5 51.44,153.67 51.44,156.21 11.43,196.22 13.34,198.12 13.34,200.66 10.79,203.2 8.89,201.3 6.35,201.3 5.08,202.56 3.17,200.66 3.17,199.39 4.45,198.12 4.45,194.31 B32.E2
N$22  (via drill 0.61)
  Top 0.152: v119.38,178.44 120.02,177.8 120.02,177.16 119.38,176.53 119.38,175.26 B23.M2
  Route2 0.152: B22.K2 131.44,180.34 131.44,176.53 130.18,175.26 130.18,173.36 128.91,172.09 B22.N2
  Bottom 0.152: B22.K2 131.44,181.61 131.44,185.42 130.18,186.69 130.18,188.59 128.91,189.87 B22.F2 | v119.38,178.44 119.38,177.8 124.46,172.72 127.64,172.72 128.27,172.09 B22.N2
N$23  (via drill 0.61)
  Top 0.152: v257.18,233.05 257.18,233.68 263.52,240.03 263.52,240.66 265.43,242.57 266.06,242.57 288.93,265.43 290.19,265.43 295.91,271.14 301.62,271.14 302.26,271.78 308.61,271.78 314.96,278.13 v318.77,278.13 | v372.75,234.95 375.92,231.78 v365.76,221.62
  Route2 0.152: v257.18,233.05 239.4,215.27 241.94,212.72 241.94,205.74 233.68,197.49 233.68,194.31 B14.E2
  Bottom 0.152: v318.77,278.13 329.56,278.13 365.12,242.57 370.84,242.57 371.48,241.94 371.48,236.22 v372.75,234.95 | v365.76,221.62 365.76,219.71 375.29,210.19 375.29,207.01 381.63,200.66 381.63,198.12 382.27,197.49 B02.D2
N$24  (via drill 0.61)
  Top 0.152: v358.77,171.45 360.68,173.36 361.95,173.36 378.46,189.87 382.27,189.87 B02.F2 | v296.55,129.54 296.55,128.91 295.27,127.64 295.27,126.37 294,125.09 292.1,125.09 279.4,112.4 v277.5,112.4
  Route2 0.152: v358.77,171.45 358.77,170.18 339.09,150.5 335.92,150.5 320.68,135.25 314.32,135.25 313.69,134.62 305.44,134.62 303.53,136.53 v296.55,129.54
  Route15 0.152: v277.5,112.4 276.86,112.4 272.42,116.84 272.42,119.38 273.69,120.65 272.42,121.92 272.42,123.19 268.61,127 268.61,127.64 267.33,128.91 266.06,128.91 262.89,132.08 257.81,132.08 257.18,132.72 257.18,137.8 249.56,145.41 247.01,145.41 219.07,173.36 219.07,179.71 208.91,189.87 208.91,192.41 208.28,193.04 B16.E2
N$25  (via drill 0.61)
  Top 0.152: v322.58,128.91 323.21,129.54 323.21,130.81 332.74,140.34 332.74,141.61 342.26,151.13 342.26,153.03 358.77,169.55 365.12,169.55 369.57,173.99 369.57,175.26 376.56,182.25 377.19,182.25 378.46,183.52 382.27,183.52 B02.J2
  Route2 0.152: v282.57,161.93 280.67,161.93 269.88,151.13 267.33,151.13 257.18,140.97 256.54,140.97 250.82,135.25 v250.82,134.62
  Route15 0.152: v322.58,128.91 316.87,128.91 313.06,132.72 313.06,133.35 304.17,142.24 300.99,142.24 282.57,160.66 v282.57,161.93 | v250.82,134.62 249.56,133.35 232.41,150.5 232.41,153.03 217.81,167.64 217.81,168.91 214,172.72 213.36,172.72 204.47,181.61 204.47,182.25 201.29,185.42 200.66,185.42 199.39,186.69 199.39,188.59 201.29,190.5 199.39,192.41 196.22,192.41 195.58,193.04 B17.E2
N$26  (via drill 0.61)
  Top 0.152: v384.81,172.72 384.81,169.55 384.18,168.91 384.18,163.83 371.48,151.13 368.94,151.13 v365.12,147.32 | v359.41,147.32 353.06,147.32 346.07,140.34 346.07,135.25 332.11,121.29 331.47,121.29 330.2,120.02 330.2,119.38 v320.68,109.86 | v294,126.37 292.74,126.37 288.29,121.92 281.94,121.92 v273.69,113.67
  Route15 0.152: v231.78,149.22 229.87,149.22 218.44,160.66 218.44,161.93 214,166.37 213.36,166.37 202.56,177.16 202.56,177.8 201.29,179.07 200.03,179.07 193.68,185.42 193.04,185.42 190.5,187.96 190.5,188.59 186.69,192.41 183.51,192.41 182.88,193.04 B18.E2
  Bottom 0.152: v384.81,172.72 382.9,174.62 382.9,177.16 B02.L2 | v365.12,147.32 v359.41,147.32 | v320.68,109.86 320.68,112.4 307.98,125.09 301.62,125.09 300.99,125.73 294.64,125.73 v294,126.37 | v273.69,113.67 271.14,111.12 260.99,121.29 260.35,121.29 256.54,125.09 251.46,125.09 244.47,132.08 244.47,137.8 240.66,141.61 239.4,141.61 v231.78,149.22
N$27  (via drill 0.61)
  Top 0.152: v195.58,236.22 196.22,236.22 211.46,251.46 212.09,251.46 213.36,252.73 221.62,252.73 223.52,250.83 229.24,256.54 229.24,259.08 227.97,260.35 229.24,261.62 234.31,261.62 259.08,286.38 261.62,286.38 v264.8,289.56
  Route2 0.152: v168.28,205.74 168.28,208.28 191.13,231.14 191.13,231.78 v195.58,236.22
  Route15 0.152: v353.69,208.28 355.6,208.28 362.58,201.3 363.22,201.3 364.49,200.03 364.49,198.75 384.18,179.07 384.18,173.36 382.9,172.09 B02.N2
  Bottom 0.152: v168.28,205.74 168.28,199.39 169.54,198.12 169.54,194.31 B19.E2 | v264.8,289.56 266.7,289.56 271.78,284.48 280.67,284.48 285.75,279.4 290.19,279.4 320.68,248.92 320.68,242.57 340.36,222.89 340.36,215.27 346.07,209.55 352.43,209.55 v353.69,208.28
N$28  (via drill 0.61)
  Top 0.152: v399.42,203.84 395.61,200.03 399.42,196.22 398.14,194.94 397.51,194.94 396.88,194.31 396.88,193.68 395.61,192.41 394.97,192.41 393.06,190.5 396.24,187.33 396.24,186.69 394.97,185.42 394.33,185.42 393.06,184.15 394.33,182.88 394.33,180.34 389.89,175.9 384.81,175.9 380.37,171.45 382.27,169.55 382.27,165.74 B02.R2 | v326.39,281.94 320.68,281.94 311.79,290.83 288.29,290.83 284.48,287.02 283.21,287.02 282.57,286.38 271.78,286.38 271.14,285.75 259.08,285.75 223.52,250.19 222.25,250.19 221.62,249.56 215.9,249.56 199.39,233.05 198.12,233.05 v196.85,231.78
  Route2 0.152: v196.85,231.78 196.85,231.14 191.13,225.43 191.13,224.16 161.93,194.94 158.12,194.94 157.48,194.31 B20.E2
  Bottom 0.152: v399.42,203.84 405.13,209.55 405.13,214 400.05,219.08 394.97,219.08 364.49,249.56 358.77,249.56 v326.39,281.94
N$29  (via drill 0.61)
  Top 0.152: v295.91,228.6 297.18,228.6 302.26,233.68 304.17,233.68 308.61,229.24 v307.98,228.6 | v374.65,149.86 376.56,149.86 381.63,154.94 381.63,157.48 382.27,158.12 B02.T2
  Route2 0.152: v218.44,271.14 196.22,248.92 190.5,248.92 180.34,238.76 179.07,238.76 177.8,237.49 177.8,236.86 161.29,220.34 160.66,220.34 158.75,218.44 158.12,218.44 153.67,214 153.67,205.74 144.78,196.85 144.78,194.31 B21.E2
  Route15 0.152: v218.44,271.14 222.88,275.59 224.79,275.59 229.87,270.51 230.5,270.51 232.41,268.6 238.12,268.6 241.3,265.43 243.84,265.43 244.47,264.8 247.65,264.8 263.52,248.92 269.24,248.92 273.69,244.47 274.95,244.47 279.4,240.03 280.04,240.03 285.75,234.31 285.75,233.68 289.56,229.87 294.64,229.87 v295.91,228.6 | v321.31,210.82 321.31,209.55 v325.75,205.11 | v343.54,181.61 343.54,180.34 344.81,179.07 346.07,179.07 374.65,150.5 v374.65,149.86
  Bottom 0.152: v307.98,228.6 307.98,224.16 311.79,220.34 313.06,220.34 317.5,215.9 317.5,214.63 v321.31,210.82 | v325.75,205.11 326.39,205.11 330.83,200.66 330.83,198.12 328.93,196.22 v343.54,181.61
N$30  (via drill 0.61)
  Top 0.152: B30.J2 27.3,184.78 27.94,184.78 29.84,186.69 B30.H2
  Route2 0.152: v52.7,201.3 52.7,200.03 47.62,194.94 40.64,194.94 34.29,188.59 31.11,188.59 30.48,187.96 B30.H2
  Bottom 0.152: v52.7,201.3 53.98,200.03 53.98,198.75 59.05,193.68 61.59,196.22 64.77,196.22 B27.D2
N$32  (via drill 0.61)
  Top 0.152: v146.05,194.31 148.59,194.31 149.86,195.58 153.03,195.58 153.67,196.22 B20.D2 | B18.D2 179.07,196.22 178.44,195.58 175.26,195.58 173.35,193.68 170.81,196.22 167,196.22 B19.D2 166.37,196.22 165.74,195.58 162.56,195.58 160.02,193.04 v160.02,192.41 | v185.42,193.68 187.96,196.22 191.77,196.22 B17.D2 192.41,197.49 196.22,197.49 197.49,198.75 200.03,198.75 201.29,197.49 v201.93,198.12 | v344.81,180.34 344.17,180.34 320.68,156.84 v320.68,156.21 | v294,181.61 v271.14,158.75 | v217.17,187.33 225.43,195.58 229.24,195.58 229.87,196.22 B14.D2
  Route15 0.152: v146.05,194.31 144.15,196.22 141.6,196.22 B21.D2
  Bottom 0.152: v185.42,193.68 184.78,193.68 183.51,194.94 180.97,194.94 179.71,196.22 B18.D2 | v160.02,192.41 160.02,193.04 156.84,196.22 154.31,196.22 B20.D2 | v344.81,180.34 366.39,158.75 369.57,158.75 B03.T2 | v320.68,156.21 319.4,156.21 318.13,157.48 317.5,157.48 294,180.97 v294,181.61 | v271.14,158.75 233.04,196.85 230.5,196.85 B14.D2 | v217.17,187.33 208.28,196.22 205.1,196.22 B16.D2 204.47,197.49 203.84,198.12 v201.93,198.12
N$36  (via drill 0.61)
  Top 0.152: v46.99,155.58 46.99,156.21 67.94,177.16 67.94,180.34 B27.K2
  Bottom 0.152: B30.N2 27.3,170.81 29.21,168.91 29.84,168.91 B30.P2 30.48,167.64 31.11,167 34.29,167 45.72,155.58 v46.99,155.58
N$37  (via drill 0.61)
  Top 0.152: B30.V2 27.3,153.03 27.94,153.03 29.84,154.94 B30.U2 | v45.72,144.15 52.7,151.13 53.98,151.13 64.77,161.93 64.77,164.47 B27.R2
  Bottom 0.152: v45.72,144.15 44.45,144.15 34.29,154.31 31.11,154.31 30.48,154.94 B30.U2
N$38  (via drill 0.61)
  Route2 0.152: v240.03,184.15 v247.01,191.14
  Route15 0.152: v240.03,184.15 254,170.18 254.63,170.18 258.44,166.37 258.44,162.56 B12.S2
  Bottom 0.152: v247.01,191.14 247.01,192.41 246.38,193.04 B13.E2
N$39  (via drill 0.61)
  Top 0.152: v262.25,174.62 255.27,167.64 255.27,165.74 B12.R2
  Bottom 0.152: v262.25,174.62 257.81,179.07 257.81,179.71 253.37,184.15 252.73,184.15 245.11,191.77 241.94,191.77 240.66,190.5 241.94,189.23 243.84,189.23 245.75,187.33 B13.H2
N$40
  Bottom 0.152: B13.K2 246.38,180.34 246.38,177.8 251.46,172.72 254.63,172.72 255.27,172.09 B12.N2
N$41  (via drill 0.61)
  Top 0.152: v256.54,167 257.81,167 258.44,167.64 B12.P2
  Bottom 0.152: v256.54,167 249.56,173.99 246.38,173.99 B13.M2
N$42
  Bottom 0.152: B13.P2 246.38,167.64 249.56,167.64 254.63,162.56 254.63,160.02 255.27,159.39 B12.T2
N$43
  Bottom 0.152: B13.S2 246.38,162.56 248.92,162.56 254,157.48 257.18,157.48 258.44,156.21 B12.U2
N$45  (via drill 0.61)
  Top 0.152: B31.J2 14.61,184.78 15.24,184.78 17.14,186.69 B31.H2 17.78,187.96 18.41,188.59 21.59,188.59 39.37,206.38 v40.01,206.38
  Bottom 0.152: v40.01,206.38 48.9,197.49 52.07,197.49 B28.D2
N$46  (via drill 0.61)
  Top 0.152: v29.21,157.48 48.26,176.53 49.53,176.53 50.8,177.8 50.8,178.44 52.7,180.34 55.24,180.34 B28.K2
  Bottom 0.152: B31.N2 14.61,170.81 16.51,168.91 17.14,168.91 B31.P2 17.78,167.64 18.41,167 21.59,167 29.21,159.39 v29.21,157.48
N$47  (via drill 0.61)
  Top 0.152: B31.V2 14.61,153.03 15.24,153.03 17.14,154.94 B31.U2 | v23.5,143.51 28.57,148.59 33.02,148.59 35.56,151.13 41.27,151.13 52.07,161.93 52.07,164.47 B28.R2
  Bottom 0.152: v23.5,143.51 22.86,143.51 14.61,151.77 B31.V2
N$48  (via drill 0.61)
  Top 0.152: B23.H2 118.75,186.69 116.84,184.78 116.2,184.78 B23.J2 115.57,184.15 114.3,182.88 111.12,186.06 107.95,186.06 98.42,176.53 98.42,175.9 81.28,158.75 78.74,161.29 v78.74,163.19
  Bottom 0.152: v78.74,163.19 78.11,163.83 76.2,163.83 69.85,170.18 69.85,170.81 68.58,172.09 67.94,172.09 43.81,196.22 40.01,196.22 B29.D2
N$49  (via drill 0.61)
  Top 0.152: v146.05,274.32 v49.53,177.8 | v186.06,237.49 186.06,238.12 201.93,254 204.47,254 A16.J2 205.1,254.64 207.01,256.54 207.65,256.54 A16.H2
  Route15 0.152: v49.53,177.8 46.99,180.34 43.18,180.34 B29.K2
  Bottom 0.152: v146.05,274.32 147.32,275.59 147.96,274.95 148.59,274.95 v186.06,237.49
N$50  (via drill 0.61)
  Top 0.152: v41.27,170.81 41.91,170.81 48.26,177.16 48.26,177.8 49.53,179.07 50.16,179.07 144.78,273.69 v144.78,274.32 | v192.41,231.78 200.66,240.03 203.84,240.03 204.47,240.66 A16.N2
  Route2 0.152: v41.27,170.81 40.01,169.55 40.01,165.74 B29.R2
  Bottom 0.152: v144.78,274.32 147.32,276.86 185.42,238.76 186.06,238.76 187.32,237.49 187.32,236.86 v192.41,231.78 | A16.P2 207.65,238.76 207.01,238.76 205.1,240.66 A16.N2
N$51  (via drill 0.61)
  Top 0.152: A16.U2 207.65,224.79 205.74,222.89 205.1,222.89 A16.V2 204.47,222.89 203.2,224.16 215.9,236.86 215.9,237.49 217.81,239.4 218.44,239.4 228.6,249.56 228.6,250.19 236.22,257.81 v234.31,259.71
  Bottom 0.152: v234.31,259.71 230.5,263.52 230.5,266.06 A14.D2
N$52  (via drill 0.61)
  Top 0.152: A17.J2 192.41,254.64 193.04,254.64 194.94,256.54 A17.H2 | v217.81,238.12 229.87,250.19 233.04,250.19 A14.K2
  Bottom 0.152: v217.81,238.12 200.03,255.91 196.22,255.91 195.58,256.54 A17.H2
N$53  (via drill 0.61)
  Route2 0.152: v204.47,243.21 203.2,243.21 199.39,239.4 196.22,239.4 195.58,238.76 A17.P2
  Route15 0.152: v204.47,243.21 212.09,243.21 215.9,239.4 222.25,239.4 226.06,235.59 229.87,235.59 A14.R2
  Bottom 0.152: A17.P2 194.94,238.76 194.31,238.76 192.41,240.66 A17.N2
N$54  (via drill 0.61)
  Top 0.152: A17.V2 192.41,222.89 193.04,222.89 194.94,224.79 A17.U2 | v187.96,234.95 188.59,234.95 217.17,263.52 217.17,266.06 A15.D2
  Bottom 0.152: v187.96,234.95 188.59,234.95 191.13,232.41 191.13,231.78 193.68,229.24 193.68,227.33 194.94,226.06 A17.U2
N$55  (via drill 0.61)
  Top 0.152: A18.J2 179.71,254.64 180.34,254.64 182.25,256.54 A18.H2 182.88,257.81 183.51,258.44 186.69,258.44 193.04,264.8 199.39,264.8 v201.29,266.7
  Route15 0.152: v201.29,266.7 216.53,251.46 220.34,251.46 A15.K2
N$56  (via drill 0.61)
  Top 0.152: v385.44,144.78 382.27,144.78 379.1,147.96 v372.75,141.61 | v317.5,190.5 317.5,191.14 318.13,191.77 320.68,191.77 321.94,193.04 B07.E2 322.58,194.31 323.21,194.94 v323.21,197.49
  Route2 0.152: v298.45,225.43 298.45,224.79 294.64,220.98 294,220.98 281.31,208.28 276.86,208.28 268.61,200.03 268.61,197.49 B11.D2
  Route15 0.152: v385.44,144.78 387.35,142.88 387.35,140.34 388.62,139.06 389.25,139.06 391.16,137.16 391.16,135.89 389.89,134.62 389.89,132.72 391.8,130.81 394.97,130.81 C01.D2
  Bottom 0.152: v372.75,141.61 372.11,141.61 365.12,148.59 363.86,148.59 323.85,188.59 318.77,188.59 317.5,189.87 v317.5,190.5 | v298.45,225.43 299.72,225.43 302.26,222.89 302.26,218.44 311.15,209.55 315.6,209.55 321.31,203.84 321.31,201.3 320.04,200.03 322.58,197.49 v323.21,197.49
N$57  (via drill 0.61)
  Top 0.152: v287.02,149.22 v294.64,156.84 | v311.15,148.59 312.42,149.86 314.32,149.86 319.4,154.94 321.94,154.94 B07.U2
